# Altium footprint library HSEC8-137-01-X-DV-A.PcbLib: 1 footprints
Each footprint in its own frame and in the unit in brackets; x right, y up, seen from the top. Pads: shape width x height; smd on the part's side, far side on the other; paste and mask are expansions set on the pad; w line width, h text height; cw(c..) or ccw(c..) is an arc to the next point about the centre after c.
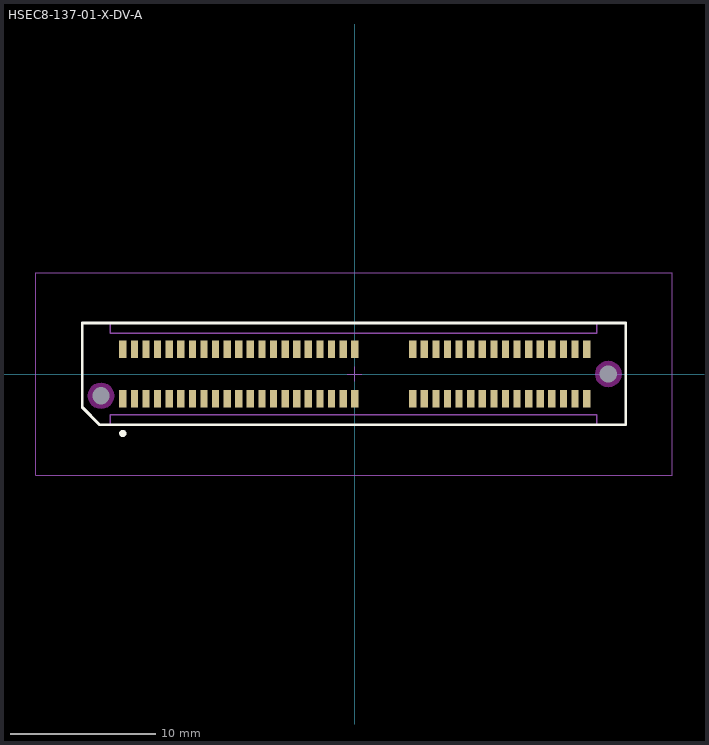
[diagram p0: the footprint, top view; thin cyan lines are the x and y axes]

## HSEC8-137-01-X-DV-A [mm] "0.80mm pitch, 74 pin, hi-speed micro edge card; w/alignment pins"
height 7.98
pads (76):
  rect 0.5x1.2 smd mask+0: 1(-16,-1.7) 2(-16,1.7) 3(-15.2,-1.7) 4(-15.2,1.7) 5(-14.4,-1.7) 6(-14.4,1.7) 7(-13.6,-1.7) 8(-13.6,1.7) 9(-12.8,-1.7) 10(-12.8,1.7) 11(-12,-1.7) 12(-12,1.7) 13(-11.2,-1.7) 14(-11.2,1.7) 15(-10.4,-1.7) 16(-10.4,1.7) 17(-9.6,-1.7) 18(-9.6,1.7) 19(-8.8,-1.7) 20(-8.8,1.7) 21(-8,-1.7) 22(-8,1.7) 23(-7.2,-1.7) 24(-7.2,1.7) 25(-6.4,-1.7) 26(-6.4,1.7) 27(-5.6,-1.7) 28(-5.6,1.7) 29(-4.8,-1.7) 30(-4.8,1.7) 31(-4,-1.7) 32(-4,1.7) 33(-3.2,-1.7) 34(-3.2,1.7) 35(-2.4,-1.7) 36(-2.4,1.7) 37(-1.6,-1.7) 38(-1.6,1.7) 39(-0.8,-1.7) 40(-0.8,1.7) 41(0,-1.7) 42(0,1.7) 43(4,-1.7) 44(4,1.7) 45(4.8,-1.7) 46(4.8,1.7) 47(5.6,-1.7) 48(5.6,1.7) 49(6.4,-1.7) 50(6.4,1.7) 51(7.2,-1.7) 52(7.2,1.7) 53(8,-1.7) 54(8,1.7) 55(8.8,-1.7) 56(8.8,1.7) 57(9.6,-1.7) 58(9.6,1.7) 59(10.4,-1.7) 60(10.4,1.7) 61(11.2,-1.7) 62(11.2,1.7) 63(12,-1.7) 64(12,1.7) 65(12.8,-1.7) 66(12.8,1.7) 67(13.6,-1.7) 68(13.6,1.7) 69(14.4,-1.7) 70(14.4,1.7) 71(15.2,-1.7) 72(15.2,1.7) 73(16,-1.7) 74(16,1.7)
  round 0.5 hole 1.2 unplated mask+0: 75(-17.5,-1.5) 76(17.5,0)
Top Overlay:
  circle w0.25: c-16,-4.1 r0.125
  lines w0.2: -18.8,-2.3 -17.6,-3.5 18.7,-3.5 18.7,3.505 -18.8,3.505 -18.8,-2.3
Keep-Out Layer:
  pour cut-out: -16.591,-1.5 -16.622,-1.265 -16.713,-1.045 -16.857,-0.857 -17.045,-0.713 -17.265,-0.622 -17.5,-0.591 -17.735,-0.622 -17.955,-0.713 -18.143,-0.857 -18.287,-1.045 -18.378,-1.265 -18.409,-1.5 -18.378,-1.735 -18.287,-1.955 -18.143,-2.143 -17.955,-2.287 -17.735,-2.378 -17.5,-2.409 -17.265,-2.378 -17.045,-2.287 -16.857,-2.143 -16.713,-1.955 -16.622,-1.735
  pour cut-out: 18.409,0 18.378,0.235 18.287,0.455 18.143,0.643 17.955,0.787 17.735,0.878 17.5,0.909 17.265,0.878 17.045,0.787 16.857,0.643 16.713,0.455 16.622,0.235 16.591,0 16.622,-0.235 16.713,-0.455 16.857,-0.643 17.045,-0.787 17.265,-0.878 17.5,-0.909 17.735,-0.878 17.955,-0.787 18.143,-0.643 18.287,-0.455 18.378,-0.235
Mechanical 12:
  lines w0.001: -18.8,-2.3 -17.6,-3.5 18.7,-3.5 18.7,3.505 -18.8,3.505 -18.8,-2.3
Mechanical 13:
  lines w0.1: -18.8,-2.3 -17.6,-3.5 -16.85,-3.5 -16.85,-2.8 16.7,-2.8 16.7,-3.5 18.7,-3.5 18.7,3.505 16.7,3.505 16.7,2.8 -16.85,2.8 -16.85,3.505 -18.8,3.5 -18.8,-2.3
  text ".Designator" at 0.254,0.254 h1.52
Mechanical 15:
  lines w0.05: -0.5,0 0.5,0 ; 0,-0.5 0,0.5 ; -22,-7 21.9,-7 21.9,7 -22,7 -22,-7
